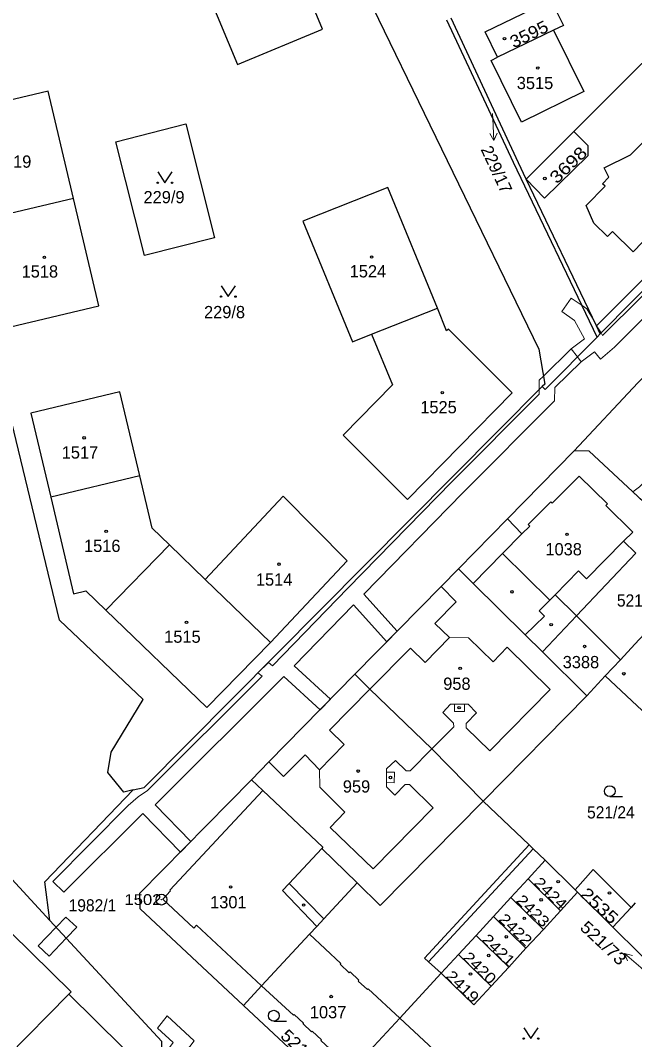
# Model space of a CAD drawing. Extents: x -679733 to -673243, y -1075091 to -1066557.
# Drawn here: x -675992.4 to -675907.2, y -1071743.4 to -1071602 of the extents above; entities that cross this region are included whole.
import ezdxf
from ezdxf.enums import TextEntityAlignment as Align

# ---------------------------------------------------------------- set-up
doc = ezdxf.new("R2010")
doc.units = 0
doc.header["$LTSCALE"] = 0.68
for name, color, linetype, lineweight in [('1', 7, 'Continuous', 25), ('13', 7, 'Continuous', 13), ('3', 7, 'Continuous', 25), ('4', 7, 'Continuous', 13), ('5', 7, 'Continuous', 25), ('7', 7, 'Continuous', 13), ('8', 7, 'Continuous', 25)]:
    doc.layers.add(name, color=color, linetype=linetype, lineweight=lineweight)
doc.layers.add('2', color=7, linetype='Continuous')

msp = doc.modelspace()

# ---------------------------------------------------------------- linework, layer by layer
at = {"layer": '1'}
for p, q in [((-675918.42, -1071603.32), (-675926.18, -1071607.06)), ((-675912.49, -1071644.37), (-675881.54, -1071613.27)), ((-675984.99, -1071626.7), (-675997.26, -1071629.6)), ((-675943.67, -1071645.52), (-675934.54, -1071641.89)), ((-675971.69, -1071674.76), (-675980.52, -1071683.79)), ((-675966.75, -1071679.53), (-675971.69, -1071674.76)), ((-675929.58, -1071680.09), (-675931.62, -1071678.07)), ((-675966.75, -1071679.53), (-675957.67, -1071688.29)), ((-675909.14, -1071690.68), (-675915.25, -1071684.61)), ((-675913.82, -1071695.69), (-675911.25, -1071692.93)), ((-675915.1, -1071722.96), (-675910.21, -1071727.8)), ((-675919.84, -1071728.11), (-675924.34, -1071723.69)), ((-675927.09, -1071735.97), (-675931.62, -1071731.6)), ((-675961.4, -1071738.66), (-675958.91, -1071735.92)), ((-675930.42, -1071749.04), (-675939.76, -1071740.42))]:
    msp.add_line(p, q, dxfattribs=at)
for points in [[(-675831.77, -1071565.57), (-675862.32, -1071595.73), (-675894.88, -1071628.17), (-675911.82, -1071645.32), (-675911.96, -1071645.47), (-675912.38, -1071645.9)], [(-676011.87, -1071581.65), (-676010.11, -1071577.99), (-675962.74, -1071567.26), (-675958.61, -1071569.02), (-675920.48, -1071647.57), (-675919.65, -1071652.44), (-675920, -1071652.79)], [(-675976.71, -1071708.75), (-675978.03, -1071709.04), (-675980.22, -1071706.33), (-675979.77, -1071703.5), (-675975.35, -1071696.19), (-675986.93, -1071685.2), (-676011.23, -1071584.45)], [(-675966.8, -1071590.47), (-675969.17, -1071591.45), (-675962.26, -1071608.09), (-675950.47, -1071603.19), (-675957.37, -1071586.56)], [(-675931.62, -1071678.07), (-675924.8, -1071671.12), (-675915.58, -1071661.71), (-675906.72, -1071652.25), (-675897.55, -1071642.97), (-675895.92, -1071641.31), (-675891.53, -1071636.88), (-675887.15, -1071632.45), (-675885.67, -1071630.95), (-675874.81, -1071619.96), (-675864.22, -1071609.24), (-675856.06, -1071600.88), (-675845.69, -1071590.25)], [(-675922.23, -1071624), (-675915.61, -1071617.37), (-675896.66, -1071598.42)], [(-675926.18, -1071607.06), (-675927.9, -1071603.57), (-675918.8, -1071599.11), (-675917.06, -1071602.66), (-675918.42, -1071603.32)], [(-675912.38, -1071645.9), (-675923.99, -1071621.69), (-675933.24, -1071601.95)], [(-675922.23, -1071624), (-675923.31, -1071621.75), (-675932.64, -1071601.66)], [(-675918.42, -1071603.32), (-675914.23, -1071611.83), (-675922.89, -1071616.07), (-675927.1, -1071607.52), (-675926.18, -1071607.06)], [(-676016.65, -1071612.42), (-675999.43, -1071687.09), (-676012.49, -1071700.56), (-675988.26, -1071726.86)], [(-675984.99, -1071626.7), (-675988.51, -1071611.8), (-676000.78, -1071614.7), (-675997.26, -1071629.6)], [(-675915.61, -1071617.37), (-675913.67, -1071619.34), (-675913.68, -1071620.76), (-675919.67, -1071626.63), (-675922.23, -1071624)], [(-675911.96, -1071645.47), (-675912.49, -1071644.37), (-675922.23, -1071624)], [(-675934.54, -1071641.89), (-675941.42, -1071625.16), (-675953.19, -1071629.84), (-675946.31, -1071646.57), (-675943.67, -1071645.52)], [(-675997.26, -1071629.6), (-675993.75, -1071644.49), (-675981.48, -1071641.59), (-675984.99, -1071626.7)], [(-675943.67, -1071645.52), (-675940.78, -1071652.55), (-675947.61, -1071659.51), (-675938.7, -1071668.46), (-675924.16, -1071653.64), (-675932.99, -1071644.79), (-675933.25, -1071645.05), (-675934.54, -1071641.89)], [(-675920, -1071652.79), (-675919.58, -1071653.19), (-675912.38, -1071645.9)], [(-675975.81, -1071665.18), (-675978.57, -1071653.51), (-675990.91, -1071656.45), (-675988.15, -1071668.13)], [(-675976.71, -1071708.75), (-675975.19, -1071708.41), (-675920, -1071652.79)], [(-675896.71, -1071677.37), (-675913.5, -1071661.73), (-675915.58, -1071661.71)], [(-675971.69, -1071674.76), (-675974.09, -1071672.44), (-675975.81, -1071665.18), (-675988.15, -1071668.13)], [(-675915.25, -1071684.61), (-675907.04, -1071675.9), (-675908.71, -1071674.24), (-675907.45, -1071672.96), (-675911.18, -1071669.27), (-675910.97, -1071669.06), (-675914.88, -1071665.19), (-675918.61, -1071668.97), (-675918.82, -1071668.76), (-675921.95, -1071671.93), (-675921.74, -1071672.14), (-675922.81, -1071673.22), (-675924.8, -1071671.12)], [(-675988.15, -1071668.13), (-675984.98, -1071681.53), (-675983.28, -1071681.13), (-675980.52, -1071683.79)], [(-675957.67, -1071688.29), (-675947.03, -1071676.96), (-675955.9, -1071667.97), (-675966.75, -1071679.53)], [(-675929.58, -1071680.09), (-675925.49, -1071675.94), (-675918.95, -1071682.4), (-675918.21, -1071681.67), (-675915.25, -1071684.61)], [(-675945.97, -1071692.7), (-675934.03, -1071680.53), (-675931.62, -1071678.07)], [(-675913.82, -1071695.69), (-675919.96, -1071689.61), (-675922.35, -1071687.25), (-675929.58, -1071680.09)], [(-675899.7, -1071680.57), (-675907.14, -1071688.53), (-675909.14, -1071690.68), (-675911.25, -1071692.93)], [(-675911.25, -1071692.93), (-675906.83, -1071697.06), (-675900.77, -1071702.73), (-675896.78, -1071698.57), (-675891.33, -1071692.89), (-675892.51, -1071691.78), (-675890.02, -1071689.11), (-675897.46, -1071682.15), (-675897.72, -1071682.43), (-675899.7, -1071680.57)], [(-675980.52, -1071683.79), (-675966.5, -1071697.32), (-675957.67, -1071688.29)], [(-675960.33, -1071707.34), (-675957.9, -1071704.86), (-675945.97, -1071692.7)], [(-675945.97, -1071692.7), (-675943.89, -1071694.77), (-675935.29, -1071703.06), (-675928.2, -1071710.3), (-675913.82, -1071695.69)], [(-675961.4, -1071738.66), (-675975.75, -1071725.24), (-675975.79, -1071723.1), (-675960.33, -1071707.34)], [(-675960.33, -1071707.34), (-675958.72, -1071708.84), (-675950.4, -1071716.68), (-675950.57, -1071716.87), (-675945.67, -1071721.66)], [(-675988.26, -1071726.86), (-675988.99, -1071721.52), (-675976.71, -1071708.75)], [(-675945.67, -1071721.66), (-675942.46, -1071724.8), (-675928.2, -1071710.3)], [(-675919.57, -1071718.52), (-675921.26, -1071716.91), (-675921.83, -1071716.37), (-675928.2, -1071710.3)], [(-675958.91, -1071735.92), (-675954.49, -1071740.01), (-675954.39, -1071739.9), (-675953.1, -1071741.1), (-675953.18, -1071741.18), (-675951.97, -1071742.3), (-675951.89, -1071742.22), (-675950.61, -1071743.41), (-675950.71, -1071743.52), (-675946.35, -1071747.56), (-675939.76, -1071740.42), (-675934.01, -1071734.18), (-675931.62, -1071731.6), (-675929.17, -1071728.94), (-675926.75, -1071726.32), (-675924.34, -1071723.69), (-675921.95, -1071721.11), (-675919.57, -1071718.52)], [(-675917.47, -1071725.53), (-675915.1, -1071722.96), (-675915.45, -1071722.61), (-675919.57, -1071718.52)], [(-675907.67, -1071725.05), (-675912.94, -1071719.79), (-675915.45, -1071722.61)], [(-675922.25, -1071730.72), (-675919.84, -1071728.11), (-675917.47, -1071725.53), (-675921.95, -1071721.11)], [(-675945.67, -1071721.66), (-675950.27, -1071726.62), (-675951.26, -1071727.68), (-675952.28, -1071728.78), (-675958.91, -1071735.92)], [(-675907.1, -1071724.43), (-675907.67, -1071725.05), (-675910.21, -1071727.8), (-675906.48, -1071731.5), (-675902.43, -1071735.52)], [(-675985.66, -1071737.08), (-675985.34, -1071736.76), (-675996.44, -1071725.86), (-675998.34, -1071727.86)], [(-676038.62, -1071840.07), (-675999.82, -1071785.34), (-675972.8, -1071746.37), (-675972.76, -1071743.68), (-675988.26, -1071726.86)], [(-675924.65, -1071733.33), (-675922.25, -1071730.72), (-675926.75, -1071726.32)], [(-675934.01, -1071734.18), (-675929.47, -1071738.55), (-675927.09, -1071735.97), (-675924.65, -1071733.33), (-675929.17, -1071728.94)], [(-675988.71, -1071759.08), (-675978.18, -1071744.43), (-675985.66, -1071737.08), (-675994.21, -1071745.77)], [(-675975.32, -1071772.82), (-675967.17, -1071764.03), (-675967.87, -1071763.39), (-675965.64, -1071760.97), (-675964.93, -1071761.62), (-675959.87, -1071756.16), (-675948.91, -1071750.35), (-675961.4, -1071738.66)]]:
    msp.add_lwpolyline(points, dxfattribs=at)
for points in [[(-675910.24, -1071631.25), (-675910.96, -1071631.94), (-675912.82, -1071630.1), (-675913.89, -1071627.65), (-675911.29, -1071624.98), (-675911.64, -1071624.63), (-675910.74, -1071623.7), (-675911.39, -1071622.42), (-675907.78, -1071620.63), (-675900.1, -1071612.84), (-675893.61, -1071619.2), (-675899.23, -1071624.94), (-675898.59, -1071625.56), (-675900.68, -1071627.72), (-675901.81, -1071630.46), (-675904.53, -1071631.6), (-675904.77, -1071631.37), (-675907.4, -1071634.06)], [(-675965.46, -1071632.12), (-675975.16, -1071634.59), (-675979.11, -1071618.82), (-675969.44, -1071616.32)]]:
    msp.add_lwpolyline(points, close=True, dxfattribs=at)
at = {"layer": '13'}
for points in [[(-675900.92, -1071635.04), (-675911.62, -1071645.67), (-675911.82, -1071645.32), (-675912.49, -1071644.37), (-675912.89, -1071643.53), (-675913.81, -1071641.99), (-675914.47, -1071641.54), (-675916, -1071640.49), (-675917.3, -1071642.38), (-675915.53, -1071643.61), (-675914.14, -1071646.14), (-675915.98, -1071647.52), (-675915.12, -1071648.67), (-675914.6, -1071649.36), (-675912.73, -1071647.96), (-675911.92, -1071648.97), (-675910, -1071647.32), (-675899.28, -1071636.66)], [(-675993.52, -1071780.38), (-675990.67, -1071776.28), (-675978.93, -1071759.77), (-675973.43, -1071752.26), (-675970.13, -1071747.16), (-675969.91, -1071745.73), (-675968.24, -1071743.58), (-675971.99, -1071740.11), (-675973.35, -1071741.79), (-675971.16, -1071743.82), (-675971.95, -1071744.85)]]:
    msp.add_lwpolyline(points, dxfattribs=at)
for points in [[(-675915.98, -1071647.52), (-675919.84, -1071651.35), (-675920.4, -1071651.91), (-675920.43, -1071653.22), (-675920.44, -1071653.82), (-675932.55, -1071666.01), (-675946.96, -1071680.77), (-675957.39, -1071691.52), (-675957.97, -1071691.05), (-675959.42, -1071692.52), (-675958.85, -1071692.98), (-675974.74, -1071708.83), (-675976.03, -1071709.72), (-675977.41, -1071710.92), (-675987.88, -1071721.44), (-675986.35, -1071722.96), (-675975.39, -1071712.02), (-675970.17, -1071717.37), (-675968.74, -1071715.91), (-675973.68, -1071710.82), (-675955.83, -1071693.01), (-675950.81, -1071697.63), (-675949.37, -1071696.16), (-675954.39, -1071691.54), (-675946.18, -1071683.07), (-675941.56, -1071688.21), (-675940.12, -1071686.74), (-675944.75, -1071681.59), (-675931.01, -1071667.53), (-675918.3, -1071654.74), (-675918.26, -1071652.89), (-675914.6, -1071649.36), (-675915.12, -1071648.67)], [(-675907.42, -1071667.4), (-675905.89, -1071668.82), (-675905.1, -1071668.19), (-675900.45, -1071663.35), (-675901.94, -1071661.93), (-675906.5, -1071666.67)], [(-675984.55, -1071727.81), (-675986.05, -1071726.39), (-675987.4, -1071727.8), (-675989.88, -1071730.4), (-675988.38, -1071731.82), (-675985.99, -1071729.32)]]:
    msp.add_lwpolyline(points, close=True, dxfattribs=at)
at = {"layer": '3'}
for p, q in [((-675910.633, -1071709.67), (-675908.883, -1071709.67)), ((-675957.223, -1071740.83), (-675955.473, -1071740.83))]:
    msp.add_line(p, q, dxfattribs=at)
for points in [[(-675973.32, -1071622.999), (-675972.32, -1071624.5), (-675971.32, -1071622.999)], [(-675964.53, -1071638.789), (-675963.53, -1071640.29), (-675962.53, -1071638.789)], [(-675922.56, -1071741.759), (-675921.56, -1071743.26), (-675920.56, -1071741.759)]]:
    msp.add_lwpolyline(points, dxfattribs=at)
for centre, radius in [((-675973.32, -1071624.4995), 0.1), ((-675971.32, -1071624.4995), 0.1), ((-675964.53, -1071640.2895), 0.1), ((-675962.53, -1071640.2895), 0.1), ((-675910.6329, -1071708.9198), 0.75), ((-675957.2229, -1071740.0798), 0.75), ((-675922.56, -1071743.2595), 0.1), ((-675920.56, -1071743.2595), 0.1)]:
    msp.add_circle(centre, radius, dxfattribs=at)
at = {"layer": '4'}
for p, q in [((-675925.49, -1071675.94), (-675922.81, -1071673.22)), ((-675913.87, -1071679.44), (-675908.71, -1071674.24)), ((-675918.21, -1071681.67), (-675914.96, -1071678.36)), ((-675914.96, -1071678.36), (-675913.87, -1071679.44)), ((-675934.03, -1071680.53), (-675931.93, -1071682.65)), ((-675931.93, -1071682.65), (-675934.91, -1071685.66)), ((-675920.41, -1071683.9), (-675918.95, -1071682.4)), ((-675922.35, -1071687.25), (-675919.68, -1071684.62)), ((-675919.68, -1071684.62), (-675920.41, -1071683.9)), ((-675919.96, -1071689.61), (-675915.25, -1071684.61)), ((-675934.91, -1071685.66), (-675932.85, -1071687.6)), ((-675936.23, -1071691.08), (-675932.85, -1071687.6)), ((-675932.85, -1071687.6), (-675930.23, -1071687.65)), ((-675930.23, -1071687.65), (-675926.78, -1071690.97)), ((-675943.89, -1071694.77), (-675938.27, -1071689.09)), ((-675938.27, -1071689.09), (-675936.23, -1071691.08)), ((-675926.78, -1071690.97), (-675924.84, -1071688.95)), ((-675924.84, -1071688.95), (-675918.9, -1071694.83)), ((-675949.51, -1071700.46), (-675943.89, -1071694.77)), ((-675927.27, -1071703.34), (-675918.9, -1071694.83)), ((-675933.79, -1071698.02), (-675932.73, -1071696.83)), ((-675932.73, -1071696.83), (-675932.18, -1071696.83)), ((-675932.18, -1071697.87), (-675932.18, -1071696.83)), ((-675932.18, -1071696.83), (-675930.78, -1071696.84)), ((-675930.78, -1071696.84), (-675930.26, -1071696.85)), ((-675930.78, -1071696.84), (-675930.78, -1071697.88)), ((-675930.26, -1071696.85), (-675929.09, -1071698.06)), ((-675932.3, -1071699.5), (-675933.79, -1071698.02)), ((-675930.78, -1071697.88), (-675932.18, -1071697.87)), ((-675930.56, -1071699.55), (-675929.09, -1071698.06)), ((-675935.29, -1071703.06), (-675932.27, -1071700.01)), ((-675932.27, -1071700.01), (-675932.3, -1071699.5)), ((-675930.55, -1071700.12), (-675930.56, -1071699.55)), ((-675927.27, -1071703.34), (-675930.55, -1071700.12)), ((-675949.51, -1071700.46), (-675947.47, -1071702.44)), ((-675947.47, -1071702.44), (-675950.89, -1071705.96)), ((-675938.3, -1071706.1), (-675935.29, -1071703.06)), ((-675955.86, -1071706.91), (-675952.89, -1071703.88)), ((-675952.89, -1071703.88), (-675950.89, -1071705.96)), ((-675941.57, -1071705.83), (-675940.36, -1071704.65)), ((-675940.36, -1071704.65), (-675938.88, -1071706.12)), ((-675957.9, -1071704.86), (-675955.86, -1071706.91)), ((-675950.85, -1071708.38), (-675950.89, -1071705.96)), ((-675941.58, -1071706.27), (-675941.57, -1071705.83)), ((-675941.6, -1071707.74), (-675941.58, -1071706.27)), ((-675941.58, -1071706.27), (-675940.5, -1071706.29)), ((-675940.5, -1071706.29), (-675940.52, -1071707.76)), ((-675938.88, -1071706.12), (-675938.3, -1071706.1)), ((-675971.64, -1071722.67), (-675958.72, -1071708.84)), ((-675950.85, -1071708.38), (-675947.37, -1071711.82)), ((-675941.61, -1071708.32), (-675941.6, -1071707.74)), ((-675940.43, -1071709.47), (-675941.61, -1071708.32)), ((-675940.52, -1071707.76), (-675941.6, -1071707.74)), ((-675940.43, -1071709.47), (-675939.01, -1071708.02)), ((-675939.01, -1071708.02), (-675938.41, -1071707.98)), ((-675938.41, -1071707.98), (-675935.11, -1071711.22)), ((-675943.45, -1071719.72), (-675935.11, -1071711.22)), ((-675947.37, -1071711.82), (-675949.39, -1071713.95)), ((-675943.45, -1071719.72), (-675949.39, -1071713.95)), ((-675955.11, -1071721.73), (-675950.57, -1071716.87)), ((-675936.33, -1071732.08), (-675921.83, -1071716.37)), ((-675935.75, -1071732.62), (-675921.26, -1071716.91)), ((-675972.59, -1071723.9), (-675971.53, -1071722.77)), ((-675971.53, -1071722.77), (-675971.64, -1071722.67)), ((-675955.11, -1071721.73), (-675956.03, -1071722.71)), ((-675956.03, -1071722.71), (-675951.26, -1071727.68)), ((-675955.11, -1071721.73), (-675950.27, -1071726.62)), ((-675972.59, -1071723.9), (-675968.33, -1071727.94)), ((-675968.33, -1071727.94), (-675967.92, -1071727.5)), ((-675967.92, -1071727.5), (-675958.91, -1071735.92)), ((-675952.28, -1071728.78), (-675947.91, -1071732.84)), ((-675947.91, -1071732.84), (-675948.01, -1071732.95)), ((-675948.01, -1071732.95), (-675946.76, -1071734.12)), ((-675935.75, -1071732.62), (-675936.33, -1071732.08)), ((-675934.01, -1071734.18), (-675935.75, -1071732.62)), ((-675946.76, -1071734.12), (-675946.65, -1071734.01)), ((-675946.65, -1071734.01), (-675945.41, -1071735.17)), ((-675945.41, -1071735.17), (-675945.51, -1071735.27)), ((-675945.51, -1071735.27), (-675944.24, -1071736.45)), ((-675944.24, -1071736.45), (-675944.14, -1071736.34)), ((-675944.14, -1071736.34), (-675939.76, -1071740.42))]:
    msp.add_line(p, q, dxfattribs=at)
at = {"layer": '5'}
for centre in [(-675925.2268, -1071604.5092), (-675920.6168, -1071608.5792), (-675919.6368, -1071623.8992), (-675989.0368, -1071634.8492), (-675943.6568, -1071634.7992), (-675933.8568, -1071653.6292), (-675983.5268, -1071659.8992), (-675980.4568, -1071672.8692), (-675916.5568, -1071673.2792), (-675956.4968, -1071677.4292), (-675924.1968, -1071681.2592), (-675969.3268, -1071685.4892), (-675918.7668, -1071685.8192), (-675914.1168, -1071688.8392), (-675931.3768, -1071691.8692), (-675908.6868, -1071692.6292), (-675931.5268, -1071697.3292), (-675945.5168, -1071706.1392), (-675941.0468, -1071707.0192), (-675917.7868, -1071721.4792), (-675963.2068, -1071722.2192), (-675910.6768, -1071723.0492), (-675920.1568, -1071724.0092), (-675953.0868, -1071724.7292), (-675922.4868, -1071726.5792), (-675924.9768, -1071729.1292), (-675927.4168, -1071731.7192), (-675929.9468, -1071734.2992), (-675949.2668, -1071737.4292)]:
    msp.add_circle(centre, 0.175, dxfattribs=at)
at = {"layer": '7'}
for p, q in [((-675926.713, -1071618.637), (-675926.265, -1071617.611)), ((-675908.585, -1071731.441), (-675908.158, -1071732.476))]:
    msp.add_line(p, q, dxfattribs=at)
for points in [[(-675926.91, -1071614.88), (-675926.87, -1071615.64), (-675926.713, -1071618.637), (-675927.265, -1071617.663)], [(-675905.71, -1071733.94), (-675906.32, -1071733.41), (-675908.585, -1071731.441), (-675907.501, -1071731.72)]]:
    msp.add_lwpolyline(points, dxfattribs=at)
at = {"layer": '8'}
for radius in [0.75, 0.03]:
    msp.add_circle((-675972.8, -1071723.9698), radius, dxfattribs=at)

# ---------------------------------------------------------------- texts
at = {"layer": '2'}
for s, height, rotation, width, p in [('3595', 1.7, 26, 1.1, (-675921.4581, -1071604.6327)), ('3698', 1.7, 44, 1.2, (-675915.796, -1071622.6313)), ('2424', 1.5, 316, 1.2, (-675919.3535, -1071723.624)), ('2535', 1.7, 317, 1.2, (-675912.6332, -1071725.441)), ('2423', 1.5, 316, 1.2, (-675921.7935, -1071726.064)), ('2422', 1.5, 316, 1.2, (-675924.2135, -1071728.674)), ('2421', 1.5, 316, 1.2, (-675926.5635, -1071731.504)), ('2420', 1.5, 316, 1.2, (-675929.1835, -1071733.984)), ('2419', 1.5, 316, 1.2, (-675931.5535, -1071736.574)), ('521/31', 1.7, 317, 1.1, (-675953.6232, -1071745.6416))]:
    msp.add_text(s, height=height, rotation=rotation, dxfattribs=dict(at, width=width)).set_placement(p, align=Align.CENTER)
for s, p in [('3515', (-675921, -1071611.499)), ('1519', (-675993.37, -1071622.41)), ('229/9', (-675972.44, -1071627.34)), ('1518', (-675989.66, -1071637.65)), ('1524', (-675944.17, -1071637.63)), ('229/8', (-675964.05, -1071643.29)), ('1525', (-675934.38, -1071656.489)), ('1517', (-675984.1, -1071662.769)), ('1516', (-675981.01, -1071675.729)), ('1038', (-675917.03, -1071676.2)), ('1514', (-675957.17, -1071680.4)), ('1515', (-675969.89, -1071688.33)), ('3388', (-675914.63, -1071691.86)), ('958', (-675931.829, -1071694.86)), ('959', (-675945.749, -1071709.12)), ('1301', (-675963.52, -1071725.18)), ('1037', (-675949.69, -1071740.44))]:
    msp.add_text(s, height=1.7, dxfattribs=at).set_placement(p, align=Align.CENTER)
msp.add_text('229/17', height=1.7, rotation=295, dxfattribs=at).set_placement((-675928.567, -1071619.857))
at = {"layer": '2', "width": 0.95}
for s, p in [('521/25', (-675906.339, -1071683.31)), ('521/24', (-675910.479, -1071712.71)), ('1982/1', (-675982.369, -1071725.62))]:
    msp.add_text(s, height=1.7, dxfattribs=at).set_placement(p, align=Align.CENTER)
at = {"layer": '2', "width": 1.1}
msp.add_text('521/73', height=1.7, rotation=317, dxfattribs=at).set_placement((-675909.2964, -1071733.2221), align=Align.RIGHT)
at = {"layer": '8', "width": 1.15}
msp.add_text('1502', height=1.5, dxfattribs=at).set_placement((-675972.799, -1071724.72), align=Align.RIGHT)

doc.saveas('drawing.dxf')
